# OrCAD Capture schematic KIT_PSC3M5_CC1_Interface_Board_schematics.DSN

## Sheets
1 01. Title page: title: PSOC CONTROL C3M5 Interface board; rev: 03; note: 630-60702-01
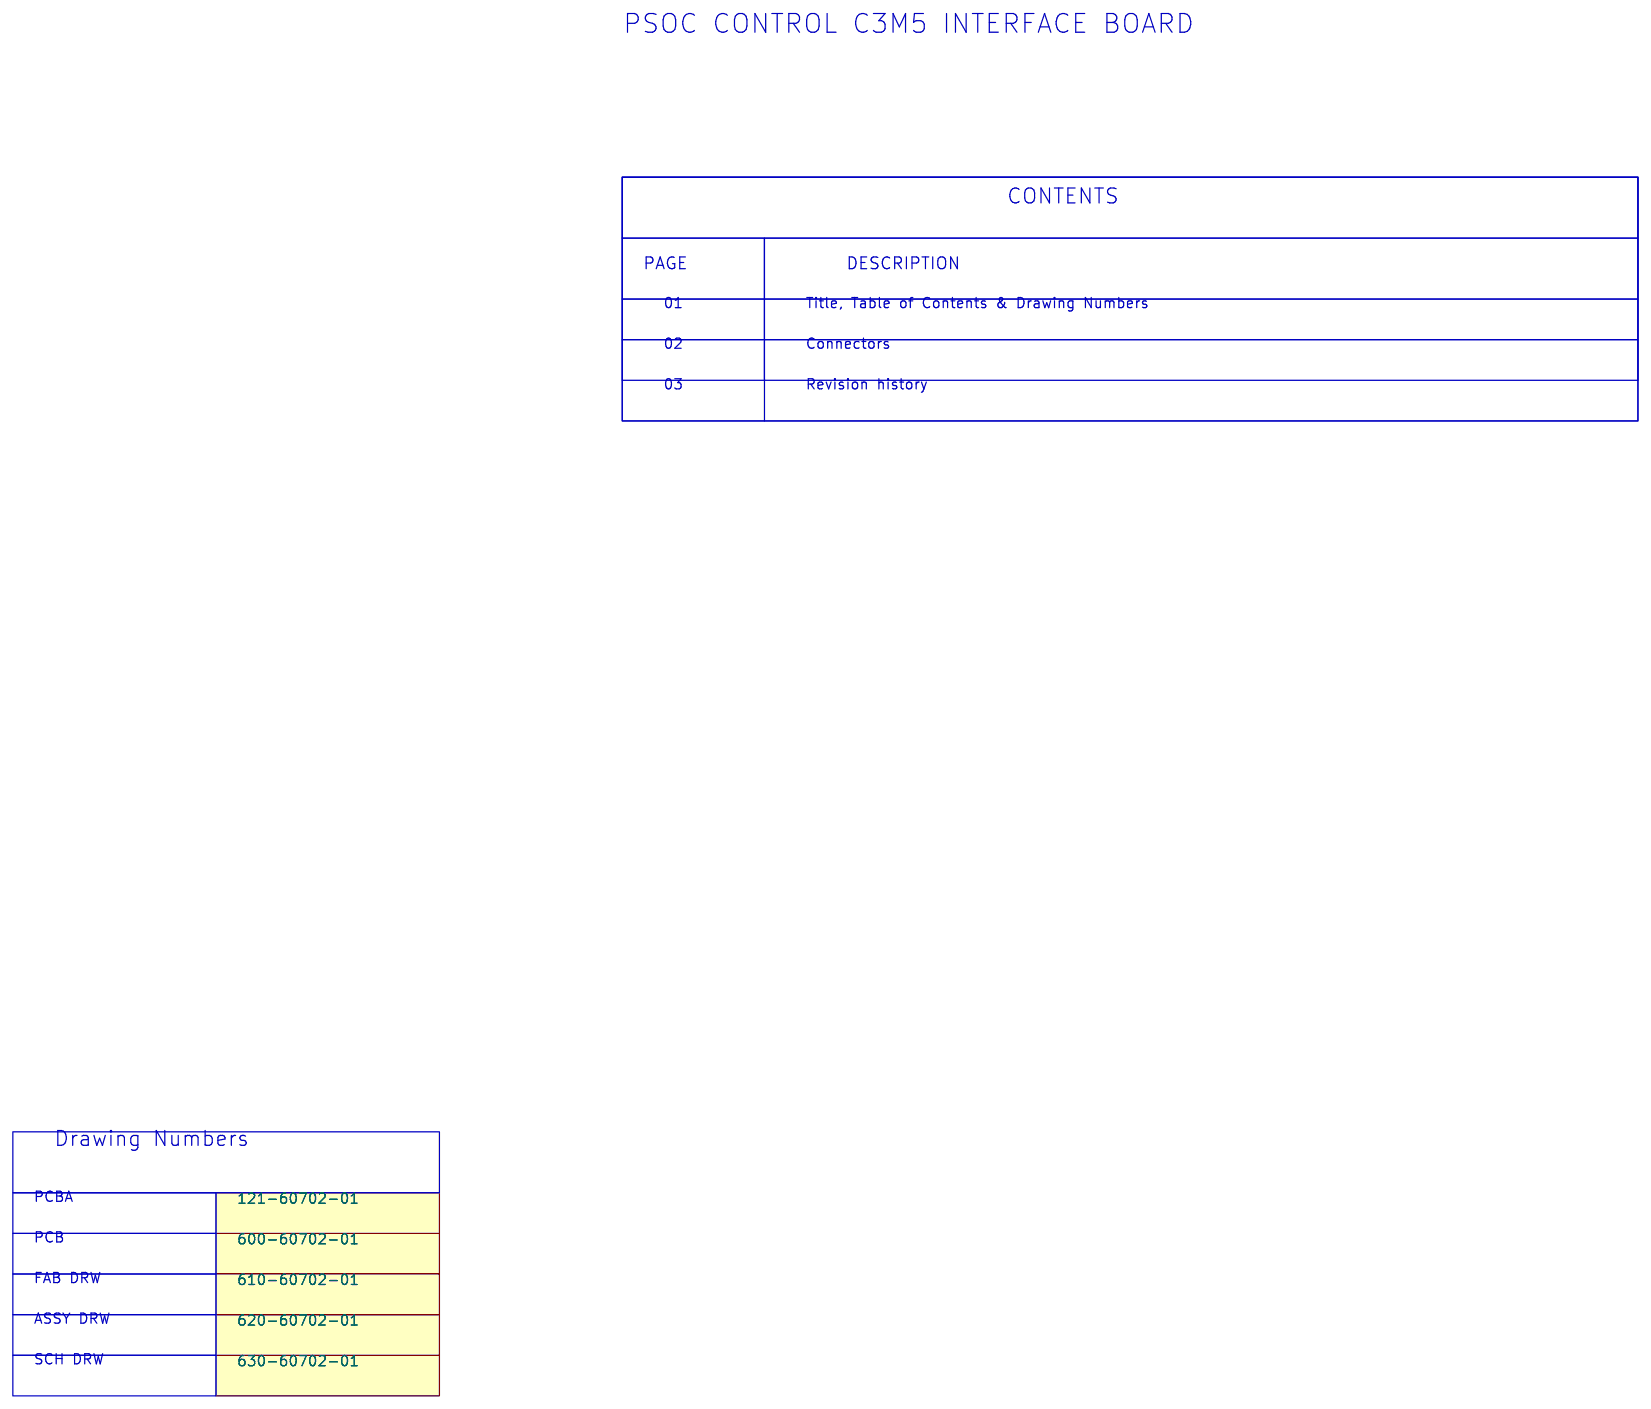
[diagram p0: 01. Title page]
2 02. Connectors: size A4
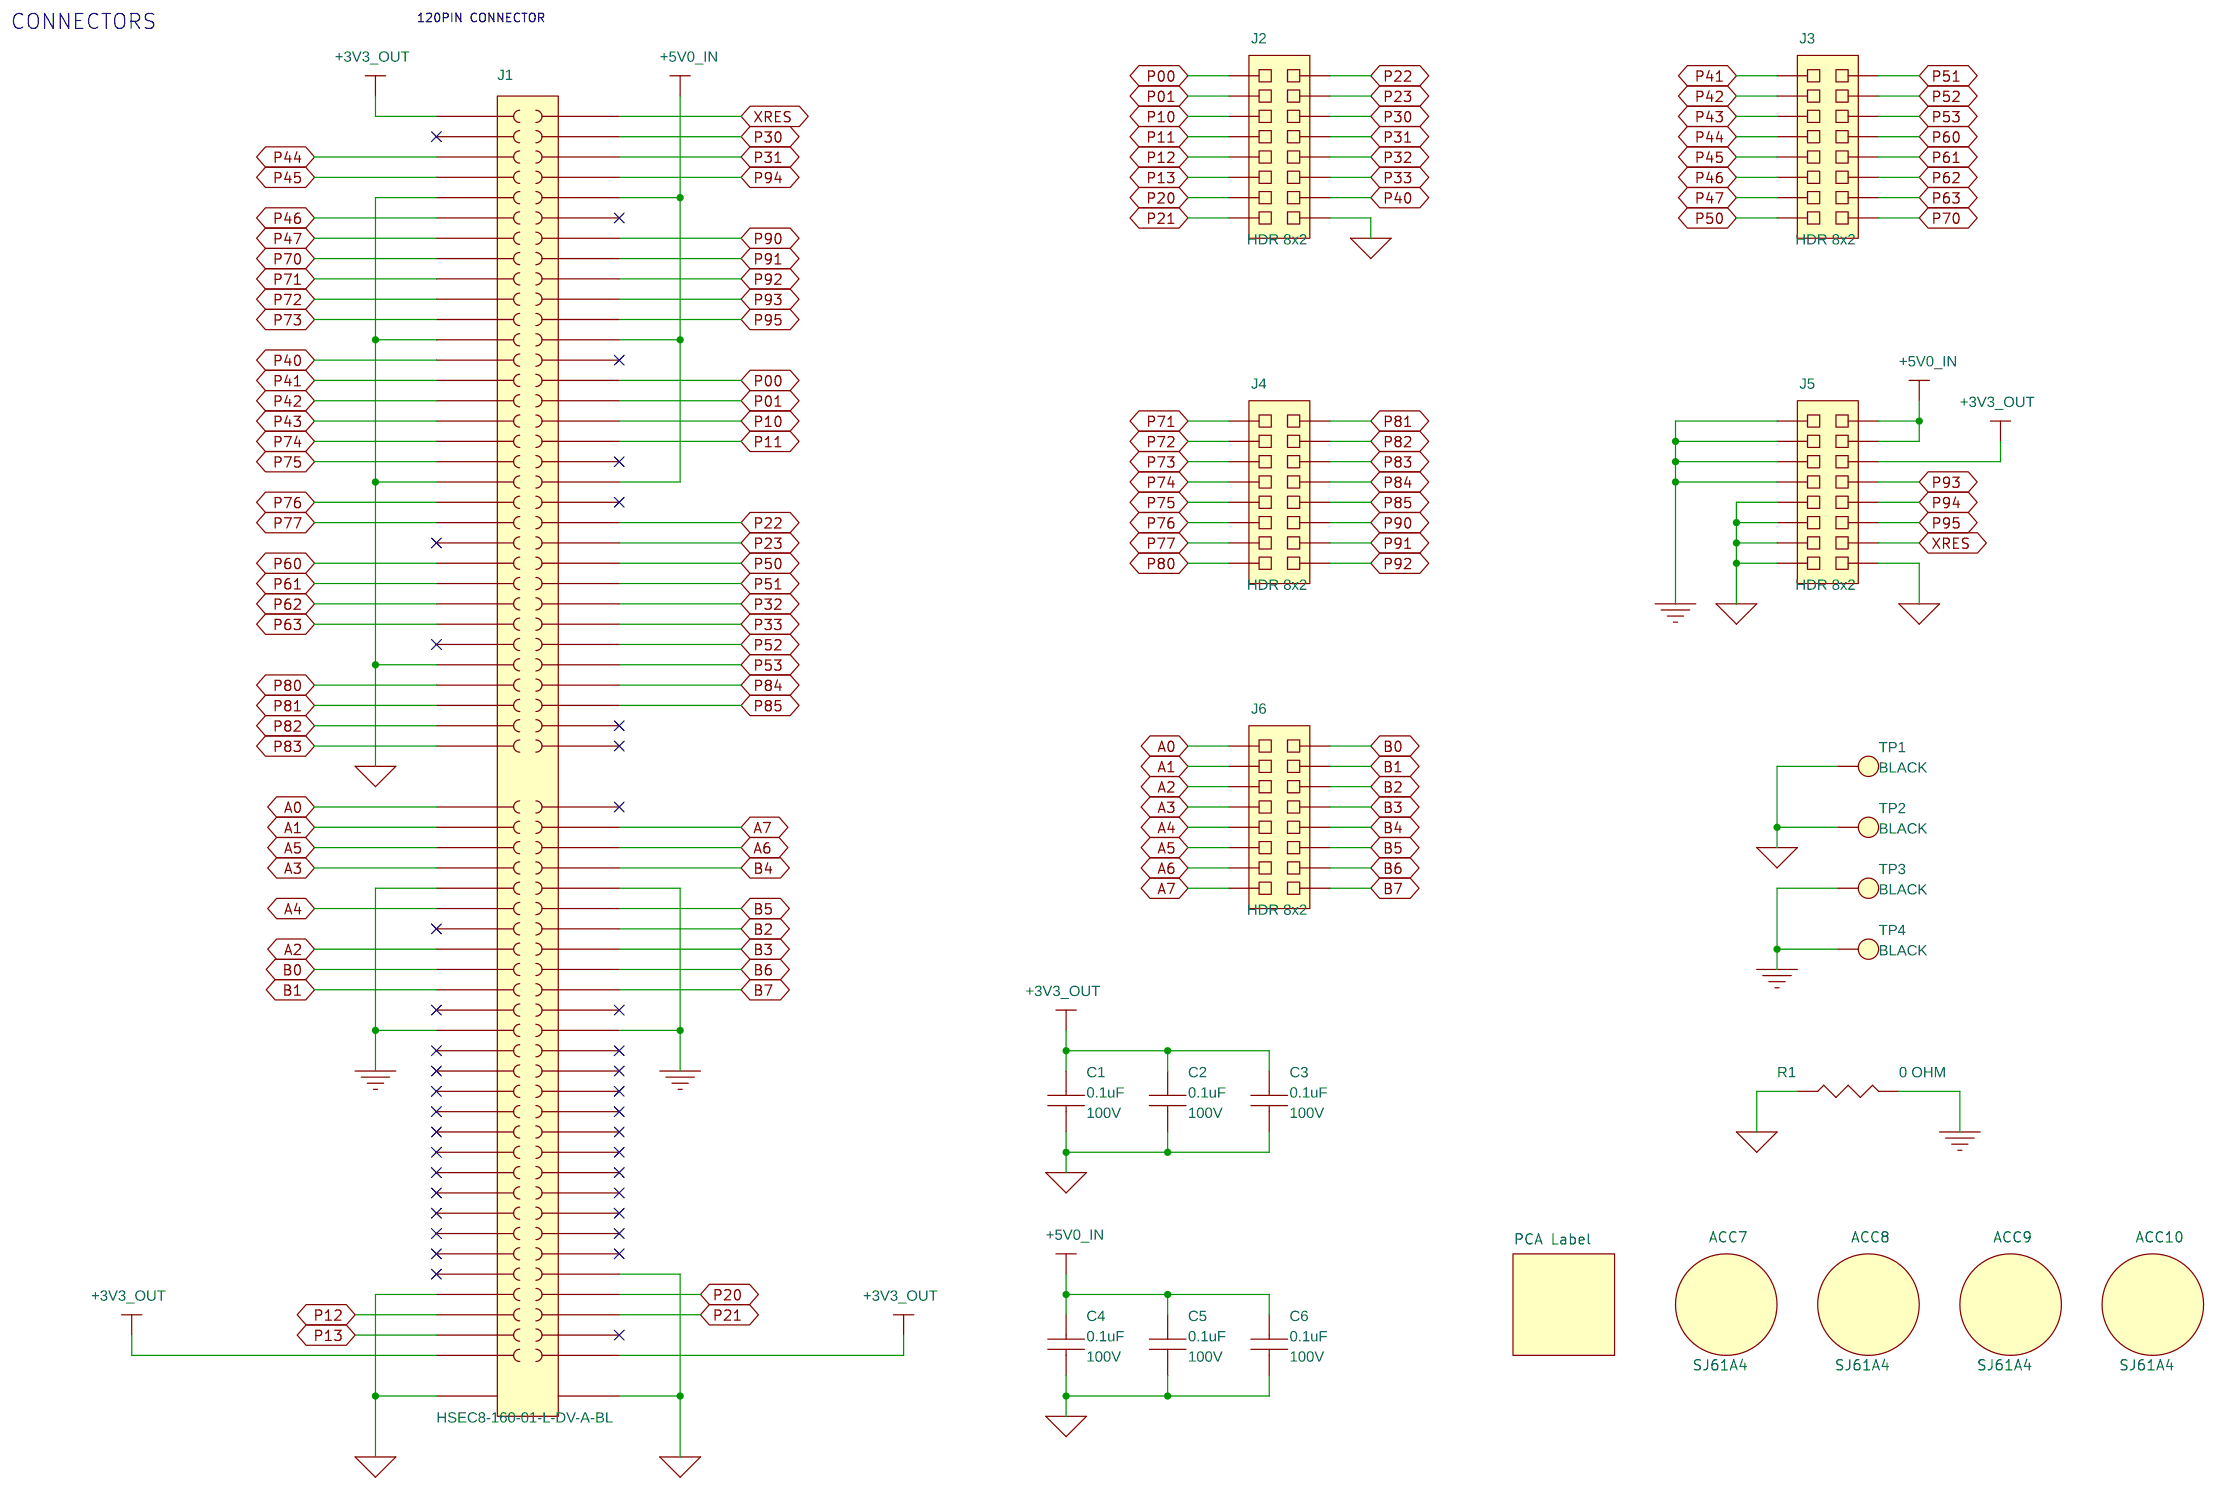
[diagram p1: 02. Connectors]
3 03. Revision history
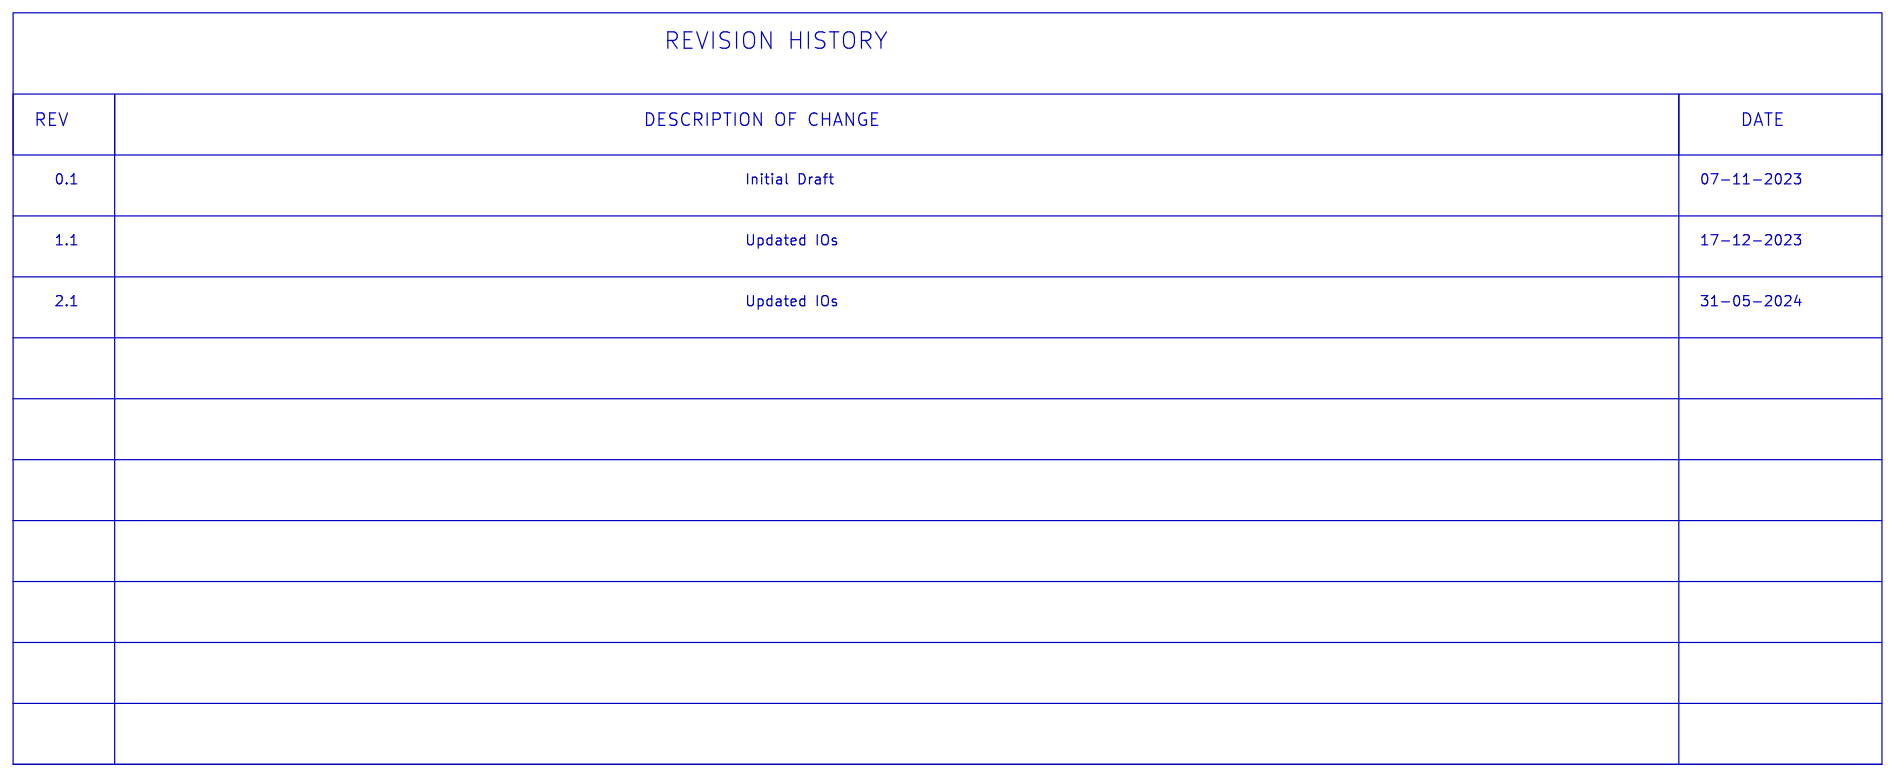
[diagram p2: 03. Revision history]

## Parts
sheet 01. Title page
ACC1  121-60702-01  [TBD]
ACC2  600-60702-01  [TBD]
ACC3  610-60702-01  [TBD]
ACC4  620-60702-01  [TBD]
ACC5  630-60702-01  [TBD]
sheet 02. Connectors
ACC6  PCA Label  [TBD]
ACC7  SJ61A4  [TBD]
ACC8  SJ61A4  [TBD]
ACC9  SJ61A4  [TBD]
ACC10  SJ61A4  [TBD]
C1  0.1uF  [CAPC2012_0805N]
C2  0.1uF  [CAPC2012_0805N]
C3  0.1uF  [CAPC2012_0805N]
C4  0.1uF  [CAPC2012_0805N]
C5  0.1uF  [CAPC2012_0805N]
C6  0.1uF  [CAPC2012_0805N]
J1  HSEC8-160-01-L-DV-A-BL  [SAMTEC_HSEC8-160-01-L-DV-A-BL]
J2  HDR 8x2  [CTST254P2X08_W515]
J3  HDR 8x2  [CTST254P2X08_W515]
J4  HDR 8x2  [CTST254P2X08_W515]
J5  HDR 8x2  [CTST254P2X08_W515]
J6  HDR 8x2  [CTST254P2X08_W515]
R1  0 OHM  [RESC3216_1206N]
TP1  BLACK  [TPT_KEY_5011]
TP2  BLACK  [TPT_KEY_5011]
TP3  BLACK  [TPT_KEY_5011]
TP4  BLACK  [TPT_KEY_5011]

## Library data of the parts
ACC1 = PCB_0: ASSY, PCBA, PSoC C3 Adaptor card; Asm_Instruction: No Load; DNI: DNI; Manufacturer: Cypress Approved CM; Manufacturer_PN: -NA-; Mfr_Name: Cypress Approved CM; Mfr_Part#: -NA-
ACC2 = PCB_0: PCB, BARE, PSoC C3 Adaptor card; Asm_Instruction: No Load; DNI: DNI; Manufacturer: Cypress Approved CM; Manufacturer_PN: -NA-; Mfr_Name: Cypress Approved CM; Mfr_Part#: -NA-
ACC3 = PCB_0: DRW, FABRICATION DRAWING, PSoC C3 Adaptor card; Asm_Instruction: No Load; DNI: DNI; Manufacturer: Cypress Approved CM; Manufacturer_PN: -NA-; Mfr_Name: Cypress Approved CM; Mfr_Part#: -NA-
ACC4 = PCB_0: DRW, ASSEMBLY DRAWING, PSoC C3 Adaptor card; Asm_Instruction: No Load; DNI: DNI; Manufacturer: Cypress Approved CM; Manufacturer_PN: -NA-; Mfr_Name: Cypress Approved CM; Mfr_Part#: -NA-
ACC5 = PCB_0: DRW, SCHEMATIC DRAWING, PSoC C3 Adaptor card; Asm_Instruction: No Load; DNI: DNI; Manufacturer: Cypress Approved CM; Manufacturer_PN: -NA-; Mfr_Name: Cypress Approved CM; Mfr_Part#: -NA-
ACC6 = LABEL: LBL, PCA Label, Vendor Code, Datecode, Serial Number (YYWWVVXXXXX); CY_PN: 899-60120-01; Manufacturer: JETech; Manufacturer_PN: 899-60120-01; Operating_Temp: NA; Part_Status: In Prod
ACC7-ACC10 = BUMPON: HW, BUMPON, CYLIN, 9.53mm DIA, 7.9MM High, BLK; CY_PN: 700-60093-01; Description1: Tapered,Polyurethane, Black; Manufacturer: 3M; Operating_Temp: -34°C to 66°C; Part_Status: In Prod
C1-C6 = CAP-NP: CAP, CER, 0.1µF, 100V, 10%, X7R, 0805; Approved: Approved; CY_PN: 510-61061-01; Device_File: 510-61061-01; Dielectric: X7R; FPLIST: CAPC2012_0805N,CAPC2012_0805M; Lifecycle: Active; Manufacturer: Wurth; Manufacturer_PN: 885012207128; Operating_Temp: -55°C ~ 125°C; Package: 0805; Part_Status: Unrel; Tolerance: 10%; Voltage: 100V
J1 = SKT-120-ODD-EVEN-HSEC8-2SH-J: CONN, EDGE, DUAL, FML ,120POS, 0.8MM, SMD; Approved: Approved; CY_PN: 720-60666-01; Conatct_Length: NA; Contact_Finish: GOLD; Device_File: 720-60666-01; Lifecycle: Active; Manufacturer: SAMTEC; Mated_Height: NA; Operating_Temp: -55°C ~ 125°C; Part_Status: Unrel; Pin_Pitch: 0.8mm; Pins: 120; Row_pitch: NA; Rows: 2; Shrouding: NA
J2-J6 = PLG-16-ODD-EVEN-J: CONN, HDR, MALE, DUAL, 16POS, 2.54mm, GOLD, STR, TH; Approved: Approved; CY_PN: 710-60122-01; Conatct_Length: 5.84mm; Contact_Finish: GOLD; Current_Rating: 3A; Device_File: 710-60122-01; FPLIST: CTST254P2X08_W515,CTST254P2X08_W515_FLIP; Lifecycle: Active; Manufacturer: Sullins; Manufacturer_PN: PBC08DAAN; Mated_Height: NA; Operating_Temp: -65°C ~ 125°C; Part_Status: Unrel; Pin_Pitch: 2.54mm; Pins: 16; Row_pitch: 2.54mm; Rows: 2; Shrouding: NA
R1 = RES: RES, FIXED, 0 OHM, JUMPER, 3/4W, 1206; Approved: Approved; CY_PN: 500-60896-01; Device_File: 500-60896-01; Lifecycle: Active; Manufacturer: Stackpole; Manufacturer_PN: HCJ1206ZT0R00; Operating_Temp: -55°C ~ 155°C; Package: 1206; Part_Status: Unrel; Rating: 3/4W; Tolerance: JUMPER
TP1-TP4 = TP: TEST POINT, PC, MULTIPURPOSE, BLACK; Approved: Approved; CY_PN: 711-60014-01; Description1: NA; Device_File: 711-60014-01; Lifecycle: NA; Manufacturer: Keystone; Manufacturer_PN: 5011; Part_Status: In Des

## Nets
+3V3_OUT: C1.1 C2.1 C3.1 J1.1 J1.119 J1.120 J5.6
+5V0_IN: C4.1 C5.1 C6.1 J1.10 J1.24 J1.38 J5.2 J5.4
AGND: J1.73 J1.74 J1.87 J1.88 J5.1 J5.3 J5.5 J5.7 R1.2 TP3.1(TP) TP4.1(TP)
GND_SIGNAL: C1.2 C2.2 C3.2 C4.2 C5.2 C6.2 J1.9 J1.23 J1.37 J1.55 J1.112 J1.113 J1.SH1 J1.SH2 J2.16 J5.9 J5.11 J5.13 J5.15 J5.16 R1.1 TP1.1(TP) TP2.1(TP)
A0: J1.65 J6.1
A1: J1.67 J6.3
A2: J1.79 J6.5
A3: J1.71 J6.7
A4: J1.75 J6.9
A5: J1.69 J6.11
A6: J1.70 J6.13
A7: J1.68 J6.15
B0: J1.81 J6.2
B1: J1.83 J6.4
B2: J1.78 J6.6
B3: J1.80 J6.8
B4: J1.72 J6.10
B5: J1.76 J6.12
B6: J1.82 J6.14
B7: J1.84 J6.16
P00: J1.28 J2.1
P01: J1.30 J2.3
P10: J1.32 J2.5
P11: J1.34 J2.7
P12: J1.115 J2.9
P13: J1.117 J2.11
P20: J1.114 J2.13
P21: J1.116 J2.15
P22: J1.42 J2.2
P23: J1.44 J2.4
P30: J1.4 J2.6
P31: J1.6 J2.8
P32: J1.50 J2.10
P33: J1.52 J2.12
P40: J1.25 J2.14
P41: J1.27 J3.1
P42: J1.29 J3.3
P43: J1.31 J3.5
P44: J1.5 J3.7
P45: J1.7 J3.9
P46: J1.11 J3.11
P47: J1.13 J3.13
P50: J1.46 J3.15
P51: J1.48 J3.2
P52: J1.54 J3.4
P53: J1.56 J3.6
P60: J1.45 J3.8
P61: J1.47 J3.10
P62: J1.49 J3.12
P63: J1.51 J3.14
P70: J1.15 J3.16
P71: J1.17 J4.1
P72: J1.19 J4.3
P73: J1.21 J4.5
P74: J1.33 J4.7
P75: J1.35 J4.9
P76: J1.39 J4.11
P77: J1.41 J4.13
P80: J1.57 J4.15
P81: J1.59 J4.2
P82: J1.61 J4.4
P83: J1.63 J4.6
P84: J1.58 J4.8
P85: J1.60 J4.10
P90: J1.14 J4.12
P91: J1.16 J4.14
P92: J1.18 J4.16
P93: J1.20 J5.8
P94: J1.8 J5.10
P95: J1.22 J5.12
XRES: J1.2 J5.14

Not connected (* = marked no-connect by the designer): J1 3* 12* 26* 36* 40* 43* 53* 62* 64* 66* 77* 85* 86* 89* 90* 91* 92* 93* 94* 95* 96* 97* 98* 99* 100* 101* 102* 103* 104* 105* 106* 107* 108* 109* 110* 111* 118*

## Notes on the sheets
sheet 1
- PSOC CONTROL C3M5 INTERFACE BOARD
- CONTENTS
- PAGE
- DESCRIPTION
- 01
- Title, Table of Contents & Drawing Numbers
- 02
- Connectors
- 03
- Revision history
- Drawing Numbers
- PCBA
- PCB
- FAB DRW
- ASSY DRW
- SCH DRW
sheet 2
- CONNECTORS
- 120PIN CONNECTOR
sheet 3
- REVISION HISTORY
- REV
- DESCRIPTION OF CHANGE
- DATE
- 0.1
- Initial Draft
- 07-11-2023
- 1.1
- Updated IOs
- 17-12-2023
- 2.1
- Updated IOs
- 31-05-2024
